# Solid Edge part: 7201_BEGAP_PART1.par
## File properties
Author: PARTuser1
Template: Normal.par
Last saved by: Francesco
Revision: 3
Application: Solid Edge
Material: Acciaio
Stile della faccia: Acciaio
Stile di riempimento: ANSI32(Acciaio)
Stile virtuale: Acciaio lavorato a macchina
Coef. of Thermal Exp: 0.0
Thermal Conductivity: 32.0
Specific Heat: 481.0
Modulus of Elasticity: 199947953000.0
Poisson's Ratio: 0.29
Yield Stress: 262000766.0
Ultimate Stress: 358527364.0
Elongation: 0.0
Tipo di contenuto documento: 0
Density: 7833,000 kg/m^3
Accuracy: 0,990
CADENASNORM: 7201 BEGAP_PART1
CADENAS_NB: 7201 BEGAP_PART1
CADENAS_NN: _PART1
CADENAS_NBSYN: 7201 BEGAP_PART1
CADENAS_LINA: 7201 BEGAP_PART1
CADENAS_Z: 10.000
CADENAS_Y0W2: 10.604
CADENAS_XIP: 0.000
CADENAS_XIN: 0.000
CADENAS_YIAC: 10.100
CADENAS_HIAC: 4.100
CADENAS_BEAC: 10.000
CADENAS_HI1: 2.250
CADENAS_R2I: 0.200
CADENAS_RWB: 3.000
CADENAS_XEP: 0.000
CADENAS_R2E: 0.100
CADENAS_Z0W2: 3.446
CADENAS_XEN: 0.000
CADENAS_RI: 3.000
CADENAS_X0WB: 5.000
CADENAS_RE: 3.000
CADENAS_C1E: 0.000
CADENAS_HE2: -16.000
CADENAS_HE1: 1.900
CADENAS_YEAC: 12.550
CADENAS_HEAC: 3.450
CADENAS_X0W2: 5.000
CADENAS_BOREDIAMETER: 12.000
CADENAS_BIAC: 10.000
CADENAS_BCH: 0.000
CADENAS_R1I: 0.600
CADENAS_PRODUCTID: 1210023201.000
CADENAS_BEARINGWIDTH: 10.000
CADENAS_R1E: 0.300
CADENAS_Y0WE: 11.150
CADENAS_Y0WB: 11.150
CADENAS_X0IP: 5.000
CADENAS_Y0IAC: 11.150
CADENAS_comment: design:acbb1; version:5000.3; lang:it; selectedUnitParts:000000; action:download; skf2d3daction.jsp version:2008-03-06; getRequestURI:/skf/skf3dnew/skf2d3daction.jsp
CADENAS_KT: DUMMY
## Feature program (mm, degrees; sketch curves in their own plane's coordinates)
sketch for "unnamed RevolvedProtrusion 1" plane through (0, 0, 0) normal (0, 0, 1) x-axis (1, 0, 0)
  arc centre (0.6, 6.6) radius 0.6 from (0, 6.6) to (0.6, 6) ccw
  line (0.6, 6) -> (9.4, 6)
  arc centre (9.4, 6.6) radius 0.6 from (9.4, 6) to (10, 6.6) ccw
  line (10, 6.6) -> (10, 10.1)
  line (10, 10.1) -> (7.8102, 10.1)
  arc centre (5, 11.15) radius 3 from (7.8102, 10.1) to (4.2319, 8.25) cw
  line (4.2319, 8.25) -> (0, 8.25)
  line (0, 8.25) -> (0, 6.6)
revolve "unnamed RevolvedProtrusion 1" add finite 360 deg about sketch line (10, 0) -> (0, 0)
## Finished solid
Body 1: solid body, 8 faces, 8 edges, 0 vertices.
  Faces by surface: cylinder 3, torus 3, plane 2
  Edges by curve: circle 8
Bounding box of the edges (mm; curved faces can reach further): 10.000 x 20.200 x 20.200, from (0, -10.1, -10.1) to (10, 10.1, 10.1).
Cylindrical faces by radius (mm): R6 x1, R8.25 x1, R10.1 x1
Toroidal faces (ring radius, tube radius in mm): R6.6 r0.6 x2, R11.15 r3 x1
Planar faces by outward normal: +x 1, -x 1
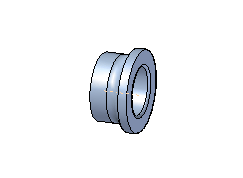
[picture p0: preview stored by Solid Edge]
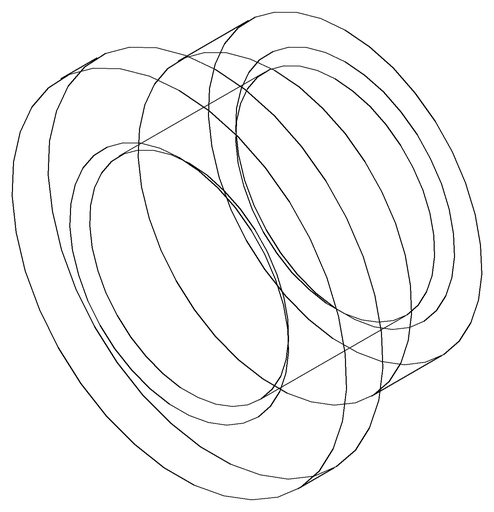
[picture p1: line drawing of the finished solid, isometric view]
